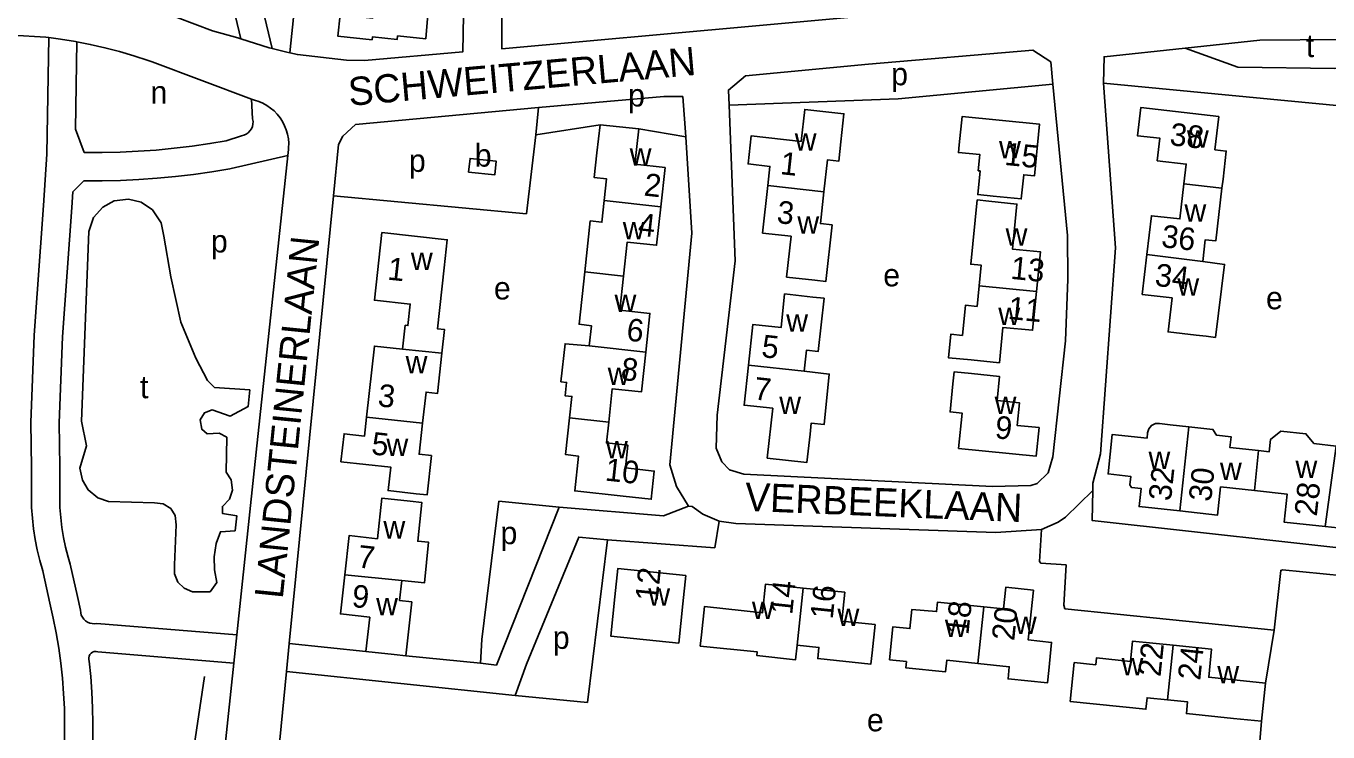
# Model space of a CAD drawing. Extents: x 161093 to 163177, y 379000 to 380904.
# Drawn here: x 162248.8 to 162479, y 380515.9 to 380640.8 of the extents above; entities that cross this region are included whole.
import ezdxf

# ---------------------------------------------------------------- set-up
doc = ezdxf.new("R2010")
doc.units = 0
for name, color, linetype in [('BLT_Basislijn', 7, 'Continuous'), ('BLT_Bebouwing', 7, 'Continuous'), ('BLT_Centroide', 7, 'Continuous'), ('BLT_Huisnummer', 7, 'Continuous'), ('BLT_Onderverdeling_panden', 7, 'Continuous'), ('BLT_Straatnaam', 7, 'Continuous')]:
    doc.layers.add(name, color=color, linetype=linetype)

msp = doc.modelspace()

# ---------------------------------------------------------------- linework, layer by layer
at = {"layer": 'BLT_Basislijn'}
for p, q in [((162252.32, 380638.79), (162252.85, 380638.72)), ((162286.26, 380638.64), (162286.79, 380638.47)), ((162286.79, 380638.47), (162291.84, 380636.91)), ((162257.84, 380637.95), (162257.6, 380622.52)), ((162291.84, 380636.91), (162292.33, 380636.79)), ((162292.33, 380636.79), (162294.92, 380636.14)), ((162271.13, 380634.42), (162288.69, 380627.83)), ((162489, 380625.9), (162439.32, 380630.67)), ((162288.69, 380627.83), (162289.2, 380627.64)), ((162288.9, 380624.33), (162288.69, 380627.83)), ((162339.42, 380626.35), (162338.98, 380621.48)), ((162257.6, 380622.52), (162259.13, 380618.39)), ((162350.32, 380623.29), (162338.98, 380621.48)), ((162365.48, 380621.14), (162357.17, 380622.55)), ((162284.23, 380620.46), (162286.94, 380621.32)), ((162285.13, 380615.54), (162295.11, 380617.87)), ((162295.11, 380617.87), (162289.05, 380560.92)), ((162295.22, 380618.91), (162295.11, 380617.87)), ((162259.05, 380613.39), (162257.1, 380611.43)), ((162303.17, 380610.74), (162295.38, 380531.5)), ((162249.82, 380562.68), (162249.82, 380559.36)), ((162254.82, 380562.78), (162254.82, 380559.17)), ((162289.05, 380560.92), (162286.1, 380533.03)), ((162251.89, 380544.05), (162253.05, 380538.64)), ((162256.66, 380545.56), (162257.91, 380539.83)), ((162257.91, 380539.83), (162258.47, 380537.4)), ((162261.35, 380535.08), (162286.1, 380533.03)), ((162286.1, 380533.03), (162285.57, 380528.05)), ((162469.52, 380533.87), (162467.98, 380524.49)), ((162261.52, 380530.05), (162285.57, 380528.05)), ((162294.9, 380526.57), (162295.38, 380531.5)), ((162308.93, 380530.11), (162295.38, 380531.5)), ((162329.17, 380528.02), (162315.98, 380529.33)), ((162280.39, 380525.7), (162278.05, 380510.07)), ((162335.31, 380522.33), (162294.9, 380526.57)), ((162467.28, 380517.75), (162464.76, 380488.53))]:
    msp.add_line(p, q, dxfattribs=at)
for points in [[(162295.46, 380636.01), (162304.37, 380721.94), (162315.24, 380730.53)], [(162264.57, 380704.6), (162287.12, 380658.77), (162292.33, 380636.79)], [(162458.95, 380647.95), (162429.2, 380645.44), (162427.8, 380666.02), (162425.43, 380681.74), (162423.8, 380684.63), (162422.56, 380686.13), (162420.55, 380688.02), (162418.06, 380689.25), (162413.44, 380690.18), (162368.4, 380693.69), (162339.82, 380697.42), (162336.03, 380696.95), (162333.77, 380695.77), (162331.31, 380693.12), (162329.69, 380689.49), (162328.59, 380681.48), (162326.85, 380664.09), (162326.39, 380655.74), (162326.05, 380636.17), (162308.65, 380634.63), (162305.5, 380634.73), (162296.83, 380635.69), (162295.46, 380636.01)], [(162263.64, 380695.17), (162282.39, 380657.07), (162286.79, 380638.47)], [(162420.27, 380663.65), (162420.98, 380655.53), (162421.46, 380644.73), (162332.97, 380636.71), (162332.97, 380650.75), (162333.38, 380662.14), (162335.17, 380682.97), (162335.46, 380684.68), (162337.94, 380687.54), (162339.78, 380688.85), (162343.17, 380689.54), (162388.27, 380684.36), (162412.11, 380682.92), (162415.13, 380681.97), (162417.98, 380678.84), (162418.87, 380675.08), (162420.27, 380663.65)], [(162286.26, 380638.64), (162281.79, 380639.92), (162272.42, 380643.46), (162266.95, 380645.14), (162258.88, 380647)], [(162252.32, 380638.79), (162246.39, 380639.16), (162245.22, 380639.18), (162243.86, 380638.9), (162242.74, 380638.43), (162241.84, 380637.82), (162241.6, 380637.62)], [(162252.85, 380638.72), (162252.53, 380618.1), (162251.93, 380608.99), (162250.27, 380586.06), (162249.67, 380570.59), (162249.82, 380562.68)], [(162252.85, 380638.72), (162254.95, 380638.43), (162257.57, 380638), (162257.84, 380637.95)], [(162453.75, 380636.83), (162466.99, 380638.23), (162481.2, 380638.39), (162495.33, 380634.77)], [(162257.84, 380637.95), (162260.18, 380637.49), (162262.77, 380636.9), (162265.34, 380636.23), (162267.9, 380635.49), (162270.42, 380634.67), (162271.13, 380634.42)], [(162295.46, 380636.01), (162294.92, 380636.14)], [(162397.78, 380634.03), (162426.81, 380636.5), (162430, 380634.4), (162430.38, 380630.48)], [(162439.32, 380630.67), (162439.42, 380635.33), (162453.75, 380636.83)], [(162453.75, 380636.83), (162463.08, 380633.49), (162480.2, 380633.22), (162495.33, 380634.77)], [(162373.13, 380626.74), (162373.03, 380629.41), (162376.04, 380631.93), (162397.78, 380634.03)], [(162430.38, 380630.48), (162432.98, 380603.69), (162433.02, 380595.97), (162432.6, 380585.06), (162430.38, 380564.55), (162429.52, 380561.69), (162427.62, 380559.81), (162426.51, 380559.46), (162419.73, 380559.3), (162375.77, 380561.5), (162373.22, 380562.22), (162371.85, 380563.63), (162370.83, 380566.09), (162371.02, 380571.91), (162374.18, 380599.19), (162373.13, 380626.74)], [(162373.13, 380626.74), (162403.01, 380627.88), (162430.38, 380630.48)], [(162439.32, 380630.67), (162441.46, 380601.53), (162438.78, 380565.05), (162437.43, 380559.86), (162437.42, 380558.6)], [(162289.2, 380627.64), (162289.97, 380627.4), (162290.71, 380627.09), (162291.41, 380626.7), (162292.08, 380626.24), (162292.69, 380625.72), (162293.25, 380625.15), (162293.75, 380624.52), (162294.19, 380623.84), (162294.55, 380623.12), (162294.85, 380622.37), (162295.07, 380621.6), (162295.21, 380620.8), (162295.27, 380620), (162295.25, 380619.2), (162295.22, 380618.91)], [(162339.42, 380626.35), (162361.62, 380628.28), (162364.94, 380628.26), (162365.48, 380621.14)], [(162303.17, 380610.74), (162304.06, 380619.82), (162304.86, 380621.25), (162307.09, 380623.32), (162339.42, 380626.35)], [(162286.94, 380621.32), (162287.37, 380621.43), (162287.77, 380621.62), (162288.13, 380621.88), (162288.43, 380622.2), (162288.68, 380622.57), (162288.85, 380622.98), (162288.95, 380623.41), (162288.97, 380623.86), (162288.9, 380624.33)], [(162259.13, 380618.39), (162262.32, 380618.38), (162265.5, 380618.44), (162268.68, 380618.59), (162271.86, 380618.81), (162275.02, 380619.12), (162278.19, 380619.5), (162281.34, 380619.96), (162284.23, 380620.46)], [(162303.17, 380610.74), (162337.31, 380607.55), (162338.98, 380621.48)], [(162365.48, 380621.14), (162366.53, 380604.13), (162362.67, 380563.14), (162363.85, 380559.29), (162365.98, 380555.82)], [(162259.05, 380613.39), (162262.29, 380613.38), (162265.54, 380613.44), (162268.78, 380613.59), (162272.02, 380613.81), (162275.25, 380614.11), (162278.47, 380614.5), (162281.69, 380614.96), (162284.89, 380615.5), (162285.13, 380615.54)], [(162257.1, 380611.43), (162256.92, 380608.64), (162255.27, 380585.78), (162254.67, 380570.54), (162254.82, 380562.78)], [(162500.53, 380565.43), (162491.21, 380560.22), (162490.79, 380559.37), (162489.5, 380547.52), (162437.35, 380553.26), (162437.42, 380558.6)], [(162249.82, 380559.36), (162249.79, 380557.47), (162249.83, 380555.57), (162249.96, 380553.68), (162250.17, 380551.8), (162250.45, 380549.93), (162250.82, 380548.07), (162251.26, 380546.23), (162251.78, 380544.4), (162251.89, 380544.05)], [(162254.82, 380559.17), (162254.79, 380557.38), (162254.84, 380555.6), (162254.97, 380553.82), (162255.18, 380552.04), (162255.47, 380550.28), (162255.84, 380548.53), (162256.28, 380546.8), (162256.66, 380545.56)], [(162428.39, 380551.68), (162431.32, 380552.99), (162432.62, 380553.89), (162437.42, 380558.6)], [(162343.07, 380555.62), (162332.44, 380556.68), (162329.42, 380532.21), (162329.17, 380528.02)], [(162329.17, 380528.02), (162332.01, 380527.71), (162343.07, 380555.62)], [(162343.07, 380555.62), (162361.51, 380554.11), (162365.98, 380555.82)], [(162371.39, 380553.14), (162368.47, 380554.37), (162366.63, 380555.76), (162365.98, 380555.82)], [(162371.39, 380553.14), (162370.61, 380548.46), (162351.63, 380549.83)], [(162428.39, 380551.68), (162420.31, 380551.14), (162374.3, 380552.74), (162371.39, 380553.14)], [(162428.39, 380551.68), (162428.01, 380546.01), (162428.23, 380545.75), (162432.71, 380545.43), (162432.29, 380538.31), (162432.5, 380537.66), (162469.52, 380533.87)], [(162351.63, 380549.83), (162346.55, 380550.34), (162337.3, 380527.85), (162335.31, 380522.33)], [(162351.63, 380549.83), (162348.08, 380521.1), (162335.31, 380522.33)], [(162469.52, 380533.87), (162470.66, 380544.45), (162470.95, 380544.57), (162488.98, 380542.76), (162489.07, 380542.53), (162484.46, 380499.64), (162483.46, 380487.1), (162482.67, 380486.89), (162464.76, 380488.53)], [(162253.05, 380538.64), (162253.65, 380536.02), (162254.18, 380533.38), (162254.62, 380530.72), (162254.99, 380528.06), (162255.28, 380525.39), (162255.48, 380522.7), (162255.61, 380520.02), (162255.66, 380517.33), (162255.63, 380514.64), (162255.51, 380511.95), (162255.32, 380509.27), (162255.05, 380506.59), (162254.95, 380505.81)], [(162258.47, 380537.4), (162258.5, 380536.97), (162258.61, 380536.55), (162258.8, 380536.16), (162259.05, 380535.81), (162259.37, 380535.52), (162259.73, 380535.28), (162260.13, 380535.12), (162260.55, 380535.03), (162260.99, 380535.02), (162261.35, 380535.08)], [(162261.52, 380530.05), (162261.21, 380530.1), (162260.9, 380530.08), (162260.6, 380529.98), (162260.34, 380529.8), (162260.13, 380529.57), (162259.98, 380529.29), (162259.91, 380528.98), (162259.92, 380528.67), (162259.98, 380528.42)], [(162259.98, 380528.42), (162260.27, 380525.68), (162260.48, 380522.92), (162260.61, 380520.16), (162260.66, 380517.4), (162260.63, 380514.64), (162260.52, 380511.87), (162260.33, 380509.12), (162260.06, 380506.37), (162259.92, 380505.19)], [(162285.57, 380528.05), (162283.33, 380506.85), (162282.42, 380498.27)], [(162294.9, 380526.57), (162291.65, 380493.33), (162359.14, 380485.89), (162435.1, 380482.76), (162447.03, 380482.03), (162452.42, 380480.7), (162457.34, 380476.87)]]:
    msp.add_lwpolyline(points, dxfattribs=at)
msp.add_lwpolyline([(162285.81, 380551.46), (162286.08, 380554.12), (162283.55, 380554.54), (162283.57, 380555.76), (162284.8, 380557.03), (162285.34, 380558.65), (162285.08, 380560.5), (162284.2, 380561.83), (162284.36, 380568.01), (162283.01, 380568.73), (162280.84, 380568.59), (162279.89, 380569.43), (162279.61, 380571.07), (162280.36, 380572.33), (162281.74, 380572.84), (162284.93, 380571.71), (162288.09, 380573.43), (162288.4, 380576.38), (162282.14, 380576.83), (162280.9, 380578.04), (162278.84, 380581.97), (162276.18, 380588.34), (162274.45, 380596.37), (162273.17, 380603.55), (162272.7, 380605.94), (162271.2, 380608.22), (162269.2, 380609.58), (162266.93, 380610.13), (162264.42, 380609.8), (162262.41, 380608.71), (162260.78, 380606.85), (162259.93, 380604.38), (162258.66, 380570.85), (162259.51, 380566.47), (162258.34, 380562.54), (162258.79, 380560.4), (162259.83, 380558.68), (162261.54, 380557.3), (162263.42, 380556.63), (162271.52, 380556.41), (162273.09, 380556.25), (162274.42, 380555.41), (162275.19, 380554.17), (162275.36, 380552.49), (162275.08, 380545.43), (162275.09, 380543.82), (162275.7, 380542.39), (162276.77, 380541.31), (162278.27, 380540.68), (162281.39, 380540.64), (162282.58, 380542.31), (162282.15, 380544.55), (162282.11, 380546.85), (162282.48, 380549.22), (162283.19, 380551.29)], close=True, dxfattribs=at)
at = {"layer": 'BLT_Bebouwing'}
for p, q in [((162357.17, 380622.55), (162350.32, 380623.29)), ((162467.98, 380524.49), (162467.28, 380517.75))]:
    msp.add_line(p, q, dxfattribs=at)
for points in [[(162319.5, 380638.51), (162319.9, 380642.8), (162320.8, 380642.72), (162321.85, 380653.56), (162316.88, 380654.04), (162307.81, 380654.82), (162307.41, 380650.73), (162306.4, 380650.84), (162306.12, 380647.92), (162310.63, 380647.48), (162310.12, 380642.15), (162304.35, 380642.71), (162303.97, 380638.93), (162310.03, 380638.32), (162310.08, 380638.82), (162314.48, 380638.39), (162314.52, 380638.99), (162319.5, 380638.51)], [(162389.9, 380611.44), (162390.51, 380617.08), (162392.54, 380616.86), (162392.91, 380620.27), (162393.45, 380625.24), (162386.5, 380626), (162385.88, 380620.34), (162377.03, 380621.3), (162376.49, 380616.35), (162380.34, 380615.93), (162379.97, 380612.52)], [(162419.83, 380610.67), (162424.8, 380610.17), (162425.23, 380614.44), (162427.12, 380614.25), (162428.02, 380623.38), (162414.32, 380624.74), (162413.83, 380619.76), (162413.69, 380618.37), (162417.47, 380618), (162417.19, 380615.16), (162417.52, 380615.12), (162417.1, 380610.93), (162419.83, 380610.67)], [(162460.27, 380612.08), (162460.46, 380613.67), (162461.03, 380618.64), (162459.02, 380618.87), (162459.7, 380624.73), (162445.92, 380626.33), (162445.34, 380621.35), (162449.29, 380620.89), (162448.82, 380616.93), (162453.96, 380616.33), (162453.55, 380612.83)], [(162350.32, 380623.29), (162349.78, 380618.32), (162349.3, 380613.94), (162351.47, 380613.7), (162351.06, 380609.87)], [(162361.06, 380608.78), (162361.82, 380615.72), (162356.49, 380616.31), (162357.17, 380622.55)], [(162327.07, 380614.91), (162327.34, 380617.33), (162331.96, 380616.82), (162331.69, 380614.4), (162327.07, 380614.91)], [(162379.97, 380612.52), (162379.05, 380604.11), (162384.09, 380603.57), (162383.3, 380596.33), (162388.27, 380595.79), (162390.26, 380595.57), (162391.35, 380605.57), (162389.28, 380605.79), (162389.9, 380611.44)], [(162453.55, 380612.83), (162452.83, 380606.62), (162447.8, 380607.2), (162447, 380600.31)], [(162460.27, 380612.08), (162459.18, 380602.73), (162457.32, 380602.95), (162456.87, 380599.07)], [(162347.61, 380597.26), (162348.59, 380606.26), (162350.64, 380606.04), (162351.06, 380609.87)], [(162354.48, 380596.52), (162355.14, 380602.54), (162360.32, 380601.97), (162361.06, 380608.78)], [(162427.48, 380593.79), (162428.18, 380600.82), (162423.23, 380601.3), (162424.01, 380609.24), (162419.04, 380609.74), (162417, 380610), (162415.86, 380598.61), (162417.71, 380598.43), (162417.35, 380594.8)], [(162315.42, 380583.57), (162315.89, 380587.81), (162316.34, 380587.76), (162316.75, 380591.55), (162310.44, 380592.25), (162311.76, 380604.2), (162323.32, 380602.93), (162322.77, 380597.96)], [(162447, 380600.31), (162446.18, 380593.27), (162451.45, 380592.65), (162450.75, 380586.64), (162455.72, 380586.07), (162457.46, 380585.86), (162459.11, 380585.67), (162460.74, 380598.58), (162456.87, 380599.07)], [(162322.77, 380597.96), (162321.59, 380587.18), (162322.83, 380587.04), (162322.37, 380582.86)], [(162348.41, 380584.15), (162348.8, 380587.74), (162346.6, 380587.98), (162347.61, 380597.26)], [(162358.39, 380583.07), (162359.14, 380589.92), (162353.82, 380590.49), (162354.48, 380596.52)], [(162417.35, 380594.8), (162416.99, 380591.16), (162414.92, 380591.37), (162414.39, 380586.01), (162412.32, 380586.22), (162411.91, 380582.08), (162415.96, 380581.68), (162420.94, 380581.19), (162421.56, 380587.44), (162426.8, 380586.92), (162427.48, 380593.79)], [(162376.55, 380580.76), (162377.33, 380587.93), (162382.34, 380587.39), (162382.96, 380593.35), (162387.93, 380592.8), (162389.93, 380592.59), (162388.9, 380583.2), (162386.84, 380583.42), (162386.43, 380579.68)], [(162309.05, 380571.58), (162310.43, 380584.12), (162315.42, 380583.57)], [(162344.94, 380571.43), (162345.35, 380575.23), (162344.14, 380575.36), (162344.4, 380577.71), (162343.41, 380577.82), (162344.15, 380584.54), (162348.41, 380584.15)], [(162351.85, 380570.69), (162352.49, 380576.58), (162357.62, 380576.02), (162358.39, 380583.07)], [(162322.37, 380582.86), (162321.59, 380575.77), (162319.55, 380576), (162318.95, 380570.49)], [(162386.43, 380579.68), (162390.83, 380579.19), (162389.92, 380570.25), (162387.65, 380570.5), (162387.44, 380568.53), (162386.89, 380563.55), (162379.89, 380564.32), (162380.85, 380573.12), (162375.78, 380573.67), (162376.55, 380580.76)], [(162415.97, 380579.26), (162412.92, 380579.56), (162412.71, 380577.46), (162412.22, 380572.48), (162414.32, 380572.27), (162413.7, 380566.04), (162427.44, 380564.68), (162427.93, 380569.7), (162424.07, 380570.08), (162424.47, 380574.1), (162420.52, 380574.49), (162420.94, 380578.77), (162415.97, 380579.26)], [(162318.95, 380570.49), (162318.34, 380564.99), (162320.5, 380564.75), (162319.73, 380557.81), (162317.83, 380558.02), (162312.86, 380558.57), (162313.32, 380562.72), (162304.52, 380563.68), (162305.06, 380568.61), (162308.68, 380568.21), (162309.05, 380571.58)], [(162351.85, 380570.69), (162351.45, 380567.01), (162355.26, 380566.59), (162354.82, 380562.58), (162359.9, 380562.03), (162359.36, 380557.05), (162354.39, 380557.59), (162345.84, 380558.52), (162346.51, 380564.68), (162344.23, 380564.93), (162344.94, 380571.43)], [(162452.85, 380554.96), (162445.63, 380555.74), (162445.98, 380558.95), (162444.26, 380559.13), (162443.99, 380559.58), (162444.16, 380561.08), (162440.13, 380561.51), (162440.89, 380568.51), (162447.03, 380567.85), (162447.13, 380568.78), (162447.37, 380569.49), (162447.81, 380570.08), (162448.54, 380570.43), (162449.24, 380570.43), (162451.09, 380570.23), (162454.44, 380569.85)], [(162454.44, 380569.85), (162458.68, 380569.39), (162459.31, 380568.37), (162461.9, 380568.09), (162461.69, 380566.19), (162466.75, 380565.65)], [(162466.75, 380565.65), (162468.64, 380565.44), (162468.88, 380567.63), (162470.7, 380569.09), (162475.13, 380568.61), (162476.53, 380566.88), (162480.49, 380566.45)], [(162480.49, 380566.45), (162483.49, 380566.13), (162484.31, 380565.12), (162486.7, 380564.86), (162486.56, 380563.57), (162490.79, 380563.03), (162490.05, 380556.15), (162485.81, 380556.61), (162485.26, 380551.5), (162478.54, 380552.23)], [(162466.05, 380558.58), (162460.04, 380559.22), (162459.5, 380554.24), (162452.85, 380554.96)], [(162478.54, 380552.23), (162471.25, 380553.01), (162471.79, 380557.96), (162466.05, 380558.58)], [(162315.28, 380542.64), (162319.26, 380542.23), (162320, 380549.42), (162318.09, 380549.62), (162318.84, 380556.46), (162316.73, 380556.69), (162311.76, 380557.24), (162310.97, 380550.05), (162305.95, 380550.6), (162305.19, 380543.68)], [(162364.96, 380538.55), (162364.24, 380531.58), (162352.21, 380532.83), (162352.93, 380539.8), (162353.45, 380544.78), (162365.48, 380543.53), (162364.96, 380538.55)], [(162305.19, 380543.68), (162304.43, 380536.74), (162309.6, 380536.17), (162308.93, 380530.11)], [(162315.28, 380542.64), (162314.89, 380539.1), (162317.03, 380538.86), (162315.98, 380529.33)], [(162385.16, 380531.21), (162384.88, 380528.64), (162378.04, 380529.38), (162378.11, 380530.02), (162368.05, 380531.07), (162368.25, 380533.06), (162368.77, 380538.04), (162379.06, 380536.97), (162379.58, 380542.03), (162386.26, 380541.33)], [(162386.26, 380541.33), (162393.58, 380540.57), (162393.05, 380535.48), (162398.94, 380534.86), (162398.42, 380529.89), (162398.21, 380527.88), (162388.81, 380528.86), (162389.02, 380530.81), (162385.16, 380531.21)], [(162418.18, 380537.99), (162421.67, 380537.63), (162422.06, 380541.46), (162426.95, 380540.95), (162426.03, 380532.14), (162430.16, 380531.71), (162429.65, 380526.74), (162429.42, 380524.54), (162422.46, 380525.26), (162422.68, 380527.39), (162417.14, 380527.96)], [(162417.14, 380527.96), (162411.61, 380528.54), (162411.39, 380526.48), (162404.39, 380527.21), (162404.5, 380528.32), (162401.5, 380528.63), (162402.11, 380534.48), (162405.11, 380534.17), (162405.46, 380537.55), (162409.82, 380537.16), (162409.99, 380538.84), (162418.18, 380537.99)], [(162308.93, 380530.11), (162313.9, 380529.56), (162315.98, 380529.33)], [(162450.62, 380521.55), (162447.05, 380521.93), (162446.83, 380519.88), (162433.46, 380521.28), (162434.17, 380528.14), (162437.95, 380527.75), (162438.08, 380528.96), (162444.09, 380528.33), (162444.47, 380531.95), (162451.62, 380531.21)], [(162451.62, 380531.21), (162458.45, 380530.5), (162457.93, 380525.54), (162467.98, 380524.49)], [(162467.28, 380517.75), (162462.3, 380518.26), (162453.98, 380519.13), (162454.2, 380521.18), (162450.62, 380521.55)]]:
    msp.add_lwpolyline(points, dxfattribs=at)
at = {"layer": 'BLT_Onderverdeling_panden'}
for p, q in [((162389.9, 380611.44), (162379.97, 380612.52)), ((162453.55, 380612.83), (162460.27, 380612.08)), ((162351.06, 380609.87), (162361.06, 380608.78)), ((162456.87, 380599.07), (162447, 380600.31)), ((162354.48, 380596.52), (162347.61, 380597.26)), ((162417.35, 380594.8), (162427.48, 380593.79)), ((162315.42, 380583.57), (162322.37, 380582.86)), ((162348.41, 380584.15), (162358.39, 380583.07)), ((162386.43, 380579.68), (162376.55, 380580.76)), ((162318.95, 380570.49), (162309.05, 380571.58)), ((162351.85, 380570.69), (162344.94, 380571.43)), ((162454.44, 380569.85), (162452.85, 380554.96)), ((162466.05, 380558.58), (162466.75, 380565.65)), ((162480.49, 380566.45), (162478.54, 380552.23)), ((162315.28, 380542.64), (162305.19, 380543.68)), ((162385.16, 380531.21), (162386.26, 380541.33)), ((162417.14, 380527.96), (162418.18, 380537.99)), ((162450.62, 380521.55), (162451.62, 380531.21))]:
    msp.add_line(p, q, dxfattribs=at)

# ---------------------------------------------------------------- texts
at = {"layer": 'BLT_Centroide'}
for s, p in [('t', (162475.11, 380635.26)), ('p', (162401.79, 380630.27)), ('n', (162270.83, 380627.04)), ('p', (162355.27, 380626.52)), ('w', (162454.08, 380619.22)), ('b', (162328.17, 380615.88)), ('w', (162384.74, 380618.72)), ('w', (162420.86, 380617.33)), ('p', (162316.52, 380614.95)), ('w', (162355.56, 380616.05)), ('w', (162453.64, 380606.14)), ('w', (162354.34, 380603.02)), ('w', (162385.2, 380604.03)), ('p', (162281.52, 380600.69)), ('w', (162422.02, 380601.89)), ('w', (162316.88, 380597.58)), ('e', (162400.39, 380594.69)), ('e', (162331.56, 380592.38)), ('w', (162452.38, 380593.05)), ('w', (162352.88, 380590.17)), ('e', (162468.06, 380590.64)), ('w', (162420.73, 380587.84)), ('w', (162383.23, 380586.67)), ('w', (162315.94, 380579.31)), ('t', (162268.99, 380574.9)), ('w', (162351.67, 380577.27)), ('w', (162382, 380572.12)), ('w', (162420.08, 380572.12)), ('w', (162312.55, 380564.69)), ('w', (162351.36, 380564.25)), ('w', (162447.28, 380562.41)), ('w', (162459.92, 380560.44)), ('w', (162473.27, 380560.8)), ('w', (162312.02, 380550.09)), ('p', (162332.72, 380549.09)), ('w', (162310.73, 380536.52)), ('w', (162358.84, 380538.19)), ('w', (162377.18, 380535.84)), ('w', (162392.3, 380534.59)), ('w', (162411.29, 380532.66)), ('w', (162423.66, 380533.2)), ('p', (162341.97, 380530.57)), ('w', (162442.51, 380525.91)), ('w', (162459.45, 380524.47)), ('e', (162397.5, 380515.98))]:
    msp.add_text(s, height=4, dxfattribs=at).set_placement(p)
at = {"layer": 'BLT_Huisnummer'}
for s, rotation, p in [('38', 353.3595, (162450.91, 380619.7)), ('15', 354.3521, (162421.71, 380616.19)), ('1', 353.7757, (162382.06, 380614.56)), ('2', 353.778, (162357.96, 380610.77)), ('3', 353.7889, (162381.45, 380605.92)), ('4', 353.7826, (162356.91, 380603.72)), ('36', 353.3602, (162449.43, 380601.66)), ('1', 353.7205, (162312.62, 380595.91)), ('13', 354.3532, (162422.79, 380596.04)), ('34', 353.3583, (162448.29, 380594.81)), ('11', 354.3521, (162422.33, 380588.95)), ('6', 353.7808, (162354.87, 380585.12)), ('5', 353.7795, (162378.75, 380582.2)), ('8', 353.7809, (162353.88, 380578.18)), ('7', 353.7792, (162377.39, 380574.7)), ('3', 353.717, (162310.91, 380573.5)), ('9', 354.3489, (162420.02, 380567.85)), ('5', 353.7262, (162309.77, 380564.99)), ('10', 353.7804, (162351.09, 380560.36)), ('32', 83.8403, (162451.25, 380556.61)), ('30', 83.8424, (162458.35, 380556.5)), ('28', 83.8355, (162477.04, 380553.92)), ('7', 353.7272, (162307.33, 380544.98)), ('12', 84.0487, (162360.48, 380538.83)), ('9', 353.7242, (162306.31, 380538.01)), ('14', 84.0481, (162384.29, 380536.52)), ('16', 84.0534, (162391.45, 380535.73)), ('18', 84.0564, (162415.44, 380532.93)), ('20', 84.0493, (162423.54, 380531.89)), ('22', 84.0556, (162449.41, 380525.54)), ('24', 84.0608, (162456.43, 380524.9))]:
    msp.add_text(s, height=4, rotation=rotation, dxfattribs=at).set_placement(p)
at = {"layer": 'BLT_Straatnaam'}
for s, rotation, p in [('SCHWEITZERLAAN', 5.1174, (162306.02, 380626.62)), ('LANDSTEINERLAAN', 84.2106, (162294.22, 380539.32)), ('VERBEEKLAAN', 357.6592, (162375.85, 380555))]:
    msp.add_text(s, height=5, rotation=rotation, dxfattribs=at).set_placement(p)

doc.saveas('drawing.dxf')
